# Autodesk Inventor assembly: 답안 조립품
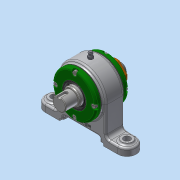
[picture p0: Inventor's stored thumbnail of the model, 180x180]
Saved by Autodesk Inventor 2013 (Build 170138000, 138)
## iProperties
Created: 2019-05
Part Number: 답안 조립품
Document SubType Name: Assembly
Designer: dgall
Author: dgall
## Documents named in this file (13)
- C:\Users\dgall\Desktop\490504V1019\답안 조립품.iam
- C:\Users\dgall\Desktop\490504V1019\본체.ipt
- C:\Users\dgall\Desktop\490504V1019\개스킷.ipt
- C:\Users\dgall\Desktop\490504V1019\그리스니플 M6.ipt
- 그리스니플  M6.ipt
- C:\Users\dgall\Desktop\490504V1019\그리스니플개스킷.ipt
- C:\Users\dgall\Desktop\490504V1019\베어링너트.ipt
- C:\Users\dgall\Desktop\490504V1019\볼트 M4.ipt
- C:\Users\dgall\Desktop\490504V1019\앵귤러 볼 베어링 7205.ipt
- C:\Users\dgall\Desktop\490504V1019\오일 실 28 40 5 B.ipt
- C:\Users\dgall\Desktop\490504V1019\축.ipt
- C:\Users\dgall\Desktop\490504V1019\칼라.ipt
- C:\Users\dgall\Desktop\490504V1019\커버.ipt
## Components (4 placed, 3 different names)
1. 개스킷:1
2. 그리스니플  M6:1
3. 그리스니플개스킷:1
4. 개스킷:2
